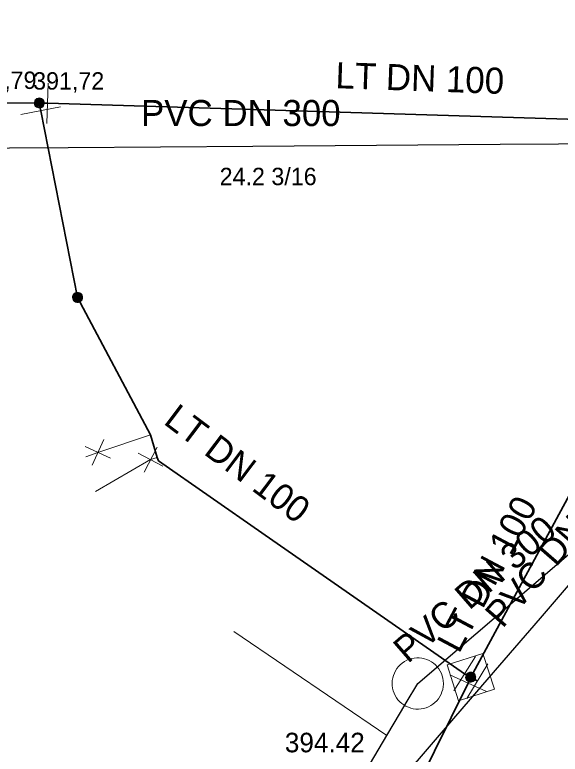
# Model space of a CAD drawing. Extents: x -772952 to -772403, y -1033777 to -1033210.
# Drawn here: x -772813.34 to -772788.23, y -1033340.97 to -1033306.93 of the extents above; entities that cross this region are included whole.
import ezdxf

# ---------------------------------------------------------------- set-up
doc = ezdxf.new("R2010")
doc.units = 0
doc.header["$LTSCALE"] = 0.36
for name, color, linetype, lineweight in [('15', 7, 'Continuous', 13), ('16', 7, 'Continuous', 35), ('2', 7, 'Continuous', 25), ('20', 7, 'Continuous', 13), ('21', 7, 'Continuous', 13), ('4', 7, 'Continuous', 13), ('57', 7, 'Continuous', 13), ('59', 7, 'Continuous', 13)]:
    doc.layers.add(name, color=color, linetype=linetype, lineweight=lineweight)
for name, color, linetype in [('17', 7, 'Continuous'), ('3', 7, 'Continuous'), ('6', 7, 'Continuous')]:
    doc.layers.add(name, color=color, linetype=linetype)

msp = doc.modelspace()

# ---------------------------------------------------------------- linework, layer by layer
at = {"layer": '15'}
for p, q in [((-772811.855, -1033311.931), (-772811.798, -1033310.069)), ((-772811.226, -1033311.162), (-772813.053, -1033311.521)), ((-772809.244, -1033326.479), (-772809.78, -1033327.665)), ((-772808.925, -1033327.337), (-772810.1, -1033326.802)), ((-772806.789, -1033326.829), (-772807.387, -1033327.985)), ((-772806.516, -1033327.702), (-772807.661, -1033327.107)), ((-772793.127, -1033338.051), (-772792.139, -1033336.473)), ((-772792.528, -1033338.402), (-772791.564, -1033336.809)), ((-772791.629, -1033338.087), (-772793.321, -1033337.31))]:
    msp.add_line(p, q, dxfattribs=at)
for points in [[(-772811.979, -1033310.991), (-772811.984, -1033310.939), (-772812.001, -1033310.889), (-772812.029, -1033310.845), (-772812.066, -1033310.807), (-772812.11, -1033310.78), (-772812.16, -1033310.762), (-772812.213, -1033310.758), (-772812.265, -1033310.764), (-772812.315, -1033310.783), (-772812.358, -1033310.812), (-772812.394, -1033310.85), (-772812.421, -1033310.895), (-772812.437, -1033310.946), (-772812.441, -1033310.998), (-772812.433, -1033311.05), (-772812.414, -1033311.099), (-772812.383, -1033311.142), (-772812.344, -1033311.177), (-772812.299, -1033311.203), (-772812.248, -1033311.218), (-772812.195, -1033311.22), (-772812.144, -1033311.211), (-772812.095, -1033311.19), (-772812.052, -1033311.16), (-772812.018, -1033311.119), (-772811.993, -1033311.073), (-772811.981, -1033311.022)], [(-772812.009, -1033310.991), (-772812.014, -1033310.942), (-772812.031, -1033310.896), (-772812.058, -1033310.855), (-772812.095, -1033310.823), (-772812.139, -1033310.801), (-772812.187, -1033310.789), (-772812.236, -1033310.789), (-772812.283, -1033310.801), (-772812.326, -1033310.825), (-772812.362, -1033310.858), (-772812.39, -1033310.898), (-772812.406, -1033310.945), (-772812.411, -1033310.994), (-772812.404, -1033311.042), (-772812.385, -1033311.087), (-772812.356, -1033311.128), (-772812.318, -1033311.159), (-772812.274, -1033311.179), (-772812.226, -1033311.19), (-772812.177, -1033311.188), (-772812.13, -1033311.174), (-772812.087, -1033311.149), (-772812.053, -1033311.116), (-772812.026, -1033311.074), (-772812.012, -1033311.027)], [(-772812.039, -1033310.991), (-772812.044, -1033310.946), (-772812.061, -1033310.903), (-772812.088, -1033310.868), (-772812.124, -1033310.841), (-772812.166, -1033310.823), (-772812.211, -1033310.818), (-772812.256, -1033310.824), (-772812.297, -1033310.842), (-772812.332, -1033310.87), (-772812.36, -1033310.907), (-772812.376, -1033310.948), (-772812.381, -1033310.993), (-772812.374, -1033311.038), (-772812.355, -1033311.08), (-772812.327, -1033311.114), (-772812.29, -1033311.14), (-772812.247, -1033311.157), (-772812.202, -1033311.16), (-772812.157, -1033311.153), (-772812.117, -1033311.133), (-772812.083, -1033311.104), (-772812.056, -1033311.066), (-772812.042, -1033311.024)], [(-772812.069, -1033310.99), (-772812.073, -1033310.949), (-772812.091, -1033310.912), (-772812.117, -1033310.881), (-772812.152, -1033310.86), (-772812.192, -1033310.848), (-772812.233, -1033310.85), (-772812.272, -1033310.862), (-772812.307, -1033310.886), (-772812.332, -1033310.918), (-772812.347, -1033310.956), (-772812.351, -1033310.997), (-772812.343, -1033311.037), (-772812.323, -1033311.073), (-772812.295, -1033311.102), (-772812.258, -1033311.122), (-772812.218, -1033311.13), (-772812.177, -1033311.126), (-772812.139, -1033311.112), (-772812.106, -1033311.086), (-772812.083, -1033311.052), (-772812.07, -1033311.013)], [(-772812.099, -1033310.99), (-772812.103, -1033310.954), (-772812.121, -1033310.922), (-772812.147, -1033310.897), (-772812.18, -1033310.881), (-772812.216, -1033310.878), (-772812.252, -1033310.886), (-772812.283, -1033310.905), (-772812.306, -1033310.933), (-772812.319, -1033310.967), (-772812.32, -1033311.004), (-772812.309, -1033311.039), (-772812.288, -1033311.068), (-772812.258, -1033311.09), (-772812.224, -1033311.1), (-772812.187, -1033311.098), (-772812.152, -1033311.085), (-772812.125, -1033311.062), (-772812.106, -1033311.03), (-772812.099, -1033310.995)], [(-772812.129, -1033310.99), (-772812.133, -1033310.959), (-772812.15, -1033310.933), (-772812.176, -1033310.915), (-772812.206, -1033310.908), (-772812.237, -1033310.912), (-772812.264, -1033310.928), (-772812.282, -1033310.952), (-772812.29, -1033310.983), (-772812.287, -1033311.013), (-772812.272, -1033311.041), (-772812.248, -1033311.061), (-772812.218, -1033311.07), (-772812.187, -1033311.067), (-772812.159, -1033311.053), (-772812.139, -1033311.03), (-772812.129, -1033311.001)], [(-772812.159, -1033310.989), (-772812.163, -1033310.965), (-772812.18, -1033310.947), (-772812.203, -1033310.938), (-772812.227, -1033310.941), (-772812.248, -1033310.955), (-772812.259, -1033310.977), (-772812.26, -1033311.002), (-772812.248, -1033311.023), (-772812.228, -1033311.037), (-772812.203, -1033311.04), (-772812.18, -1033311.031), (-772812.164, -1033311.013)], [(-772812.189, -1033310.989), (-772812.193, -1033310.974), (-772812.208, -1033310.968), (-772812.223, -1033310.972), (-772812.23, -1033310.986), (-772812.227, -1033311.001), (-772812.214, -1033311.01), (-772812.199, -1033311.007), (-772812.189, -1033310.995)], [(-772810.404, -1033320.166), (-772810.355, -1033320.15), (-772810.309, -1033320.124), (-772810.271, -1033320.087), (-772810.242, -1033320.044), (-772810.224, -1033319.994), (-772810.217, -1033319.942), (-772810.223, -1033319.889), (-772810.24, -1033319.839), (-772810.268, -1033319.795), (-772810.305, -1033319.758), (-772810.35, -1033319.731), (-772810.4, -1033319.714), (-772810.453, -1033319.708), (-772810.504, -1033319.715), (-772810.554, -1033319.733), (-772810.598, -1033319.762), (-772810.634, -1033319.801), (-772810.66, -1033319.846), (-772810.677, -1033319.896), (-772810.681, -1033319.948), (-772810.672, -1033320.001), (-772810.653, -1033320.049), (-772810.623, -1033320.092), (-772810.584, -1033320.128), (-772810.537, -1033320.154), (-772810.488, -1033320.168), (-772810.435, -1033320.17)], [(-772810.41, -1033320.137), (-772810.363, -1033320.121), (-772810.321, -1033320.096), (-772810.288, -1033320.061), (-772810.263, -1033320.018), (-772810.25, -1033319.971), (-772810.249, -1033319.922), (-772810.258, -1033319.874), (-772810.28, -1033319.83), (-772810.312, -1033319.792), (-772810.351, -1033319.763), (-772810.397, -1033319.745), (-772810.446, -1033319.738), (-772810.495, -1033319.744), (-772810.54, -1033319.76), (-772810.581, -1033319.787), (-772810.614, -1033319.824), (-772810.637, -1033319.868), (-772810.649, -1033319.915), (-772810.649, -1033319.964), (-772810.638, -1033320.011), (-772810.614, -1033320.055), (-772810.581, -1033320.092), (-772810.541, -1033320.119), (-772810.495, -1033320.136), (-772810.446, -1033320.141)], [(-772810.416, -1033320.107), (-772810.373, -1033320.093), (-772810.335, -1033320.068), (-772810.306, -1033320.034), (-772810.287, -1033319.993), (-772810.278, -1033319.949), (-772810.282, -1033319.904), (-772810.296, -1033319.861), (-772810.323, -1033319.824), (-772810.357, -1033319.795), (-772810.399, -1033319.776), (-772810.443, -1033319.768), (-772810.488, -1033319.773), (-772810.531, -1033319.789), (-772810.567, -1033319.815), (-772810.595, -1033319.85), (-772810.613, -1033319.891), (-772810.621, -1033319.937), (-772810.615, -1033319.981), (-772810.599, -1033320.024), (-772810.571, -1033320.059), (-772810.536, -1033320.087), (-772810.494, -1033320.105), (-772810.449, -1033320.111)], [(-772810.422, -1033320.078), (-772810.383, -1033320.065), (-772810.35, -1033320.04), (-772810.324, -1033320.008), (-772810.311, -1033319.969), (-772810.308, -1033319.928), (-772810.317, -1033319.888), (-772810.338, -1033319.852), (-772810.368, -1033319.824), (-772810.404, -1033319.805), (-772810.444, -1033319.798), (-772810.485, -1033319.803), (-772810.523, -1033319.819), (-772810.554, -1033319.845), (-772810.577, -1033319.879), (-772810.589, -1033319.919), (-772810.589, -1033319.96), (-772810.577, -1033319.999), (-772810.555, -1033320.034), (-772810.523, -1033320.06), (-772810.485, -1033320.076), (-772810.445, -1033320.081)], [(-772810.428, -1033320.049), (-772810.393, -1033320.037), (-772810.365, -1033320.013), (-772810.346, -1033319.982), (-772810.338, -1033319.946), (-772810.342, -1033319.91), (-772810.356, -1033319.878), (-772810.382, -1033319.851), (-772810.414, -1033319.834), (-772810.45, -1033319.828), (-772810.486, -1033319.835), (-772810.518, -1033319.852), (-772810.543, -1033319.878), (-772810.557, -1033319.912), (-772810.56, -1033319.948), (-772810.551, -1033319.984), (-772810.531, -1033320.015), (-772810.503, -1033320.037), (-772810.468, -1033320.049), (-772810.432, -1033320.049)], [(-772810.433, -1033320.019), (-772810.404, -1033320.008), (-772810.382, -1033319.986), (-772810.37, -1033319.958), (-772810.369, -1033319.927), (-772810.379, -1033319.897), (-772810.401, -1033319.874), (-772810.428, -1033319.861), (-772810.46, -1033319.859), (-772810.488, -1033319.869), (-772810.513, -1033319.889), (-772810.527, -1033319.916), (-772810.53, -1033319.947), (-772810.521, -1033319.977), (-772810.502, -1033320.002), (-772810.475, -1033320.017), (-772810.444, -1033320.021)], [(-772810.439, -1033319.99), (-772810.417, -1033319.98), (-772810.402, -1033319.96), (-772810.398, -1033319.936), (-772810.405, -1033319.913), (-772810.423, -1033319.895), (-772810.447, -1033319.888), (-772810.471, -1033319.893), (-772810.49, -1033319.909), (-772810.5, -1033319.931), (-772810.498, -1033319.956), (-772810.484, -1033319.977), (-772810.464, -1033319.989)], [(-772810.445, -1033319.96), (-772810.431, -1033319.952), (-772810.428, -1033319.937), (-772810.435, -1033319.923), (-772810.45, -1033319.918), (-772810.464, -1033319.925), (-772810.47, -1033319.94), (-772810.465, -1033319.954), (-772810.451, -1033319.961)], [(-772792.125, -1033337.419), (-772792.131, -1033337.367), (-772792.148, -1033337.317), (-772792.177, -1033337.273), (-772792.214, -1033337.236), (-772792.259, -1033337.209), (-772792.309, -1033337.192), (-772792.362, -1033337.188), (-772792.414, -1033337.195), (-772792.463, -1033337.214), (-772792.506, -1033337.243), (-772792.542, -1033337.282), (-772792.568, -1033337.327), (-772792.584, -1033337.378), (-772792.587, -1033337.43), (-772792.579, -1033337.482), (-772792.559, -1033337.531), (-772792.528, -1033337.574), (-772792.489, -1033337.608), (-772792.443, -1033337.634), (-772792.392, -1033337.648), (-772792.339, -1033337.65), (-772792.288, -1033337.64), (-772792.24, -1033337.619), (-772792.197, -1033337.588), (-772792.163, -1033337.547), (-772792.139, -1033337.501), (-772792.127, -1033337.45)], [(-772792.155, -1033337.419), (-772792.161, -1033337.37), (-772792.178, -1033337.324), (-772792.206, -1033337.284), (-772792.243, -1033337.252), (-772792.287, -1033337.23), (-772792.335, -1033337.219), (-772792.384, -1033337.219), (-772792.431, -1033337.232), (-772792.474, -1033337.256), (-772792.51, -1033337.289), (-772792.537, -1033337.33), (-772792.553, -1033337.377), (-772792.557, -1033337.426), (-772792.55, -1033337.474), (-772792.531, -1033337.519), (-772792.501, -1033337.559), (-772792.463, -1033337.59), (-772792.419, -1033337.61), (-772792.371, -1033337.62), (-772792.322, -1033337.618), (-772792.275, -1033337.603), (-772792.232, -1033337.578), (-772792.198, -1033337.544), (-772792.172, -1033337.502), (-772792.158, -1033337.455)], [(-772792.185, -1033337.419), (-772792.191, -1033337.374), (-772792.208, -1033337.332), (-772792.236, -1033337.297), (-772792.272, -1033337.27), (-772792.314, -1033337.253), (-772792.359, -1033337.248), (-772792.404, -1033337.254), (-772792.445, -1033337.273), (-772792.48, -1033337.301), (-772792.507, -1033337.338), (-772792.523, -1033337.38), (-772792.527, -1033337.425), (-772792.52, -1033337.47), (-772792.501, -1033337.511), (-772792.472, -1033337.545), (-772792.435, -1033337.571), (-772792.392, -1033337.587), (-772792.347, -1033337.59), (-772792.302, -1033337.582), (-772792.262, -1033337.562), (-772792.228, -1033337.533), (-772792.202, -1033337.495), (-772792.188, -1033337.452)], [(-772792.215, -1033337.419), (-772792.22, -1033337.378), (-772792.238, -1033337.341), (-772792.265, -1033337.31), (-772792.3, -1033337.289), (-772792.34, -1033337.278), (-772792.381, -1033337.28), (-772792.42, -1033337.293), (-772792.454, -1033337.317), (-772792.479, -1033337.349), (-772792.494, -1033337.387), (-772792.497, -1033337.428), (-772792.489, -1033337.468), (-772792.469, -1033337.504), (-772792.44, -1033337.533), (-772792.403, -1033337.552), (-772792.363, -1033337.56), (-772792.322, -1033337.556), (-772792.284, -1033337.541), (-772792.252, -1033337.515), (-772792.229, -1033337.481), (-772792.216, -1033337.442)], [(-772792.245, -1033337.419), (-772792.25, -1033337.383), (-772792.268, -1033337.351), (-772792.294, -1033337.326), (-772792.328, -1033337.311), (-772792.364, -1033337.308), (-772792.399, -1033337.316), (-772792.43, -1033337.336), (-772792.453, -1033337.364), (-772792.466, -1033337.398), (-772792.466, -1033337.435), (-772792.455, -1033337.47), (-772792.434, -1033337.499), (-772792.404, -1033337.52), (-772792.369, -1033337.53), (-772792.332, -1033337.528), (-772792.298, -1033337.514), (-772792.271, -1033337.491), (-772792.252, -1033337.459), (-772792.245, -1033337.424)], [(-772792.275, -1033337.419), (-772792.28, -1033337.388), (-772792.297, -1033337.362), (-772792.323, -1033337.345), (-772792.353, -1033337.338), (-772792.384, -1033337.342), (-772792.411, -1033337.359), (-772792.429, -1033337.383), (-772792.437, -1033337.414), (-772792.433, -1033337.444), (-772792.418, -1033337.472), (-772792.394, -1033337.491), (-772792.364, -1033337.5), (-772792.333, -1033337.497), (-772792.305, -1033337.483), (-772792.285, -1033337.459), (-772792.275, -1033337.43)], [(-772792.305, -1033337.419), (-772792.31, -1033337.395), (-772792.327, -1033337.377), (-772792.35, -1033337.368), (-772792.374, -1033337.371), (-772792.395, -1033337.385), (-772792.406, -1033337.407), (-772792.406, -1033337.432), (-772792.394, -1033337.453), (-772792.374, -1033337.467), (-772792.349, -1033337.47), (-772792.326, -1033337.461), (-772792.31, -1033337.443)], [(-772792.335, -1033337.419), (-772792.34, -1033337.404), (-772792.355, -1033337.398), (-772792.37, -1033337.402), (-772792.377, -1033337.416), (-772792.373, -1033337.431), (-772792.36, -1033337.44), (-772792.345, -1033337.437), (-772792.335, -1033337.425)]]:
    msp.add_lwpolyline(points, close=True, dxfattribs=at)
at = {"layer": '16'}
for p, q in [((-772774.629, -1033312.147), (-772811.827, -1033311.001)), ((-772786.579, -1033326.75), (-772792.355, -1033337.418)), ((-772792.633, -1033337.263), (-772792.355, -1033337.418)), ((-772792.475, -1033337.699), (-772792.355, -1033337.418)), ((-772792.355, -1033337.418), (-772792.046, -1033337.605))]:
    msp.add_line(p, q, dxfattribs=at)
for points in [[(-772830.179, -1033239.149), (-772828.5, -1033247.329), (-772824.879, -1033263.6), (-772822.929, -1033272.329), (-772821.21, -1033280.149), (-772817.589, -1033297.25), (-772817.462, -1033298.026), (-772815.385, -1033310.626), (-772815.329, -1033310.96), (-772812.21, -1033310.989), (-772811.827, -1033311.001)], [(-772812.21, -1033310.989), (-772812.14, -1033311.343), (-772810.449, -1033319.94)], [(-772810.449, -1033319.94), (-772807.094, -1033326.27), (-772806.78, -1033327.307), (-772806.73, -1033327.46), (-772801.965, -1033330.774), (-772792.633, -1033337.263)], [(-772806.021, -1033377.978), (-772805.954, -1033377.548), (-772805.072, -1033370.662), (-772803.861, -1033363.758), (-772800.241, -1033353.386), (-772792.475, -1033337.699)]]:
    msp.add_lwpolyline(points, dxfattribs=at)
at = {"layer": '2'}
for points in [[(-772776.31, -1033312.8), (-772777.043, -1033312.805), (-772777.699, -1033312.809), (-772779.326, -1033312.821), (-772784.589, -1033312.859), (-772788.311, -1033312.885), (-772790.991, -1033312.904), (-772802.376, -1033312.986), (-772810.876, -1033313.046), (-772816.3, -1033313.085), (-772821.487, -1033313.122), (-772823.628, -1033313.137), (-772826.73, -1033313.16)], [(-772774.26, -1033317.38), (-772775.055, -1033318.303), (-772775.793, -1033319.162), (-772776.724, -1033320.243), (-772778.773, -1033322.624), (-772781.051, -1033325.271), (-772783.935, -1033328.623), (-772785.839, -1033330.834), (-772789.162, -1033334.697), (-772791.52, -1033337.436), (-772793.626, -1033339.883), (-772796.031, -1033342.678), (-772798.21, -1033345.21)], [(-772794.79, -1033337.71), (-772786.885, -1033330.948), (-772785.32, -1033329.61)], [(-772806.72, -1033362.82), (-772805.427, -1033359.81), (-772802.883, -1033353.884), (-772800.283, -1033347.83), (-772798.913, -1033344.676), (-772796.212, -1033340.113), (-772795.582, -1033339.048), (-772795.322, -1033338.609), (-772794.79, -1033337.71)]]:
    msp.add_lwpolyline(points, dxfattribs=at)
at = {"layer": '21'}
msp.add_lwpolyline([(-772793.444, -1033336.86), (-772792.912, -1033338.507), (-772791.266, -1033337.975), (-772791.798, -1033336.329)], close=True, dxfattribs=at)
at = {"layer": '4'}
msp.add_lwpolyline([(-772793.61, -1033337.71), (-772793.616, -1033337.591), (-772793.634, -1033337.474), (-772793.663, -1033337.358), (-772793.704, -1033337.247), (-772793.756, -1033337.14), (-772793.819, -1033337.039), (-772793.892, -1033336.944), (-772793.973, -1033336.858), (-772794.063, -1033336.78), (-772794.161, -1033336.711), (-772794.264, -1033336.653), (-772794.373, -1033336.606), (-772794.487, -1033336.569), (-772794.603, -1033336.544), (-772794.721, -1033336.532), (-772794.84, -1033336.531), (-772794.959, -1033336.542), (-772795.075, -1033336.565), (-772795.189, -1033336.599), (-772795.299, -1033336.645), (-772795.404, -1033336.702), (-772795.502, -1033336.769), (-772795.593, -1033336.845), (-772795.676, -1033336.93), (-772795.75, -1033337.024), (-772795.814, -1033337.124), (-772795.868, -1033337.23), (-772795.911, -1033337.341), (-772795.943, -1033337.455), (-772795.962, -1033337.573), (-772795.97, -1033337.692), (-772795.966, -1033337.81), (-772795.95, -1033337.928), (-772795.922, -1033338.044), (-772795.883, -1033338.156), (-772795.832, -1033338.264), (-772795.771, -1033338.366), (-772795.7, -1033338.462), (-772795.62, -1033338.549), (-772795.531, -1033338.629), (-772795.435, -1033338.699), (-772795.332, -1033338.759), (-772795.224, -1033338.808), (-772795.111, -1033338.846), (-772794.995, -1033338.872), (-772794.877, -1033338.887), (-772794.758, -1033338.89), (-772794.64, -1033338.881), (-772794.522, -1033338.86), (-772794.408, -1033338.827), (-772794.298, -1033338.783), (-772794.192, -1033338.728), (-772794.093, -1033338.662), (-772794, -1033338.587), (-772793.916, -1033338.503), (-772793.841, -1033338.411), (-772793.775, -1033338.312), (-772793.719, -1033338.207), (-772793.675, -1033338.097), (-772793.641, -1033337.983), (-772793.62, -1033337.866), (-772793.61, -1033337.747)], close=True, dxfattribs=at)
at = {"layer": '57'}
msp.add_line((-772796.212, -1033340.113), (-772803.25, -1033335.32), dxfattribs=at)
at = {"layer": '59'}
for points in [[(-772807.094, -1033326.27), (-772809.512, -1033327.071), (-772810.064, -1033327.28)], [(-772806.781, -1033327.308), (-772807.088, -1033327.406), (-772809.617, -1033328.868)]]:
    msp.add_lwpolyline(points, dxfattribs=at)

# ---------------------------------------------------------------- texts
at = {"layer": '17'}
for rotation, p in [(358, (-772798.591, -1033310.304)), (323, (-772806.54, -1033325.729)), (62, (-772792.893, -1033336.369))]:
    msp.add_text('LT DN 100 ', height=1.2, rotation=rotation, dxfattribs=at).set_placement(p)
at = {"layer": '20'}
for s, p in [('391,79', (-772815.612, -1033310.341)), ('391,72', (-772812.492, -1033310.371))]:
    msp.add_text(s, height=0.8, dxfattribs=at).set_placement(p)
at = {"layer": '3'}
for s, height, p in [('PVC DN 300', 1.2, (-772807.527, -1033312.05)), ('24.2 3/16', 0.8, (-772803.907, -1033314.771))]:
    msp.add_text(s, height=height, dxfattribs=at).set_placement(p)
for rotation, p in [(49, (-772790.885, -1033335.207)), (41, (-772795.246, -1033336.822))]:
    msp.add_text('PVC DN 300', height=1.2, rotation=rotation, dxfattribs=at).set_placement(p)
at = {"layer": '6'}
msp.add_text('394.42', height=0.9, dxfattribs=at).set_placement((-772800.909, -1033340.879))

doc.saveas('drawing.dxf')
